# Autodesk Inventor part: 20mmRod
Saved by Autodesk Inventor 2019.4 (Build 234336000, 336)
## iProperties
Created: 2020-04
Part Number: 20mmRod
Material: Generic
Document SubType Name: Modeling
Designer: Administrator
Density: 1 g/cm^3
Appearance: Default
Title: 20mmRod v1
Author: Administrator
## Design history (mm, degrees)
feature "Body1"
body "Solid1"
